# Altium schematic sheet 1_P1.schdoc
size 309 x 223 mm; Symbol: Sheet-Symbol_A4; Device: Sheet-Symbol_A4; Company: 嘉立创EDA; Version: V1.0; Page Size: A4; @Project Name: 阿尔法波平板; @Page Count: 1; @Update Date: 2024-05-21; @Create Date: 2024-05-20; @Schematic Name: Schematic1; @Page No: 1; @Page Name: P1
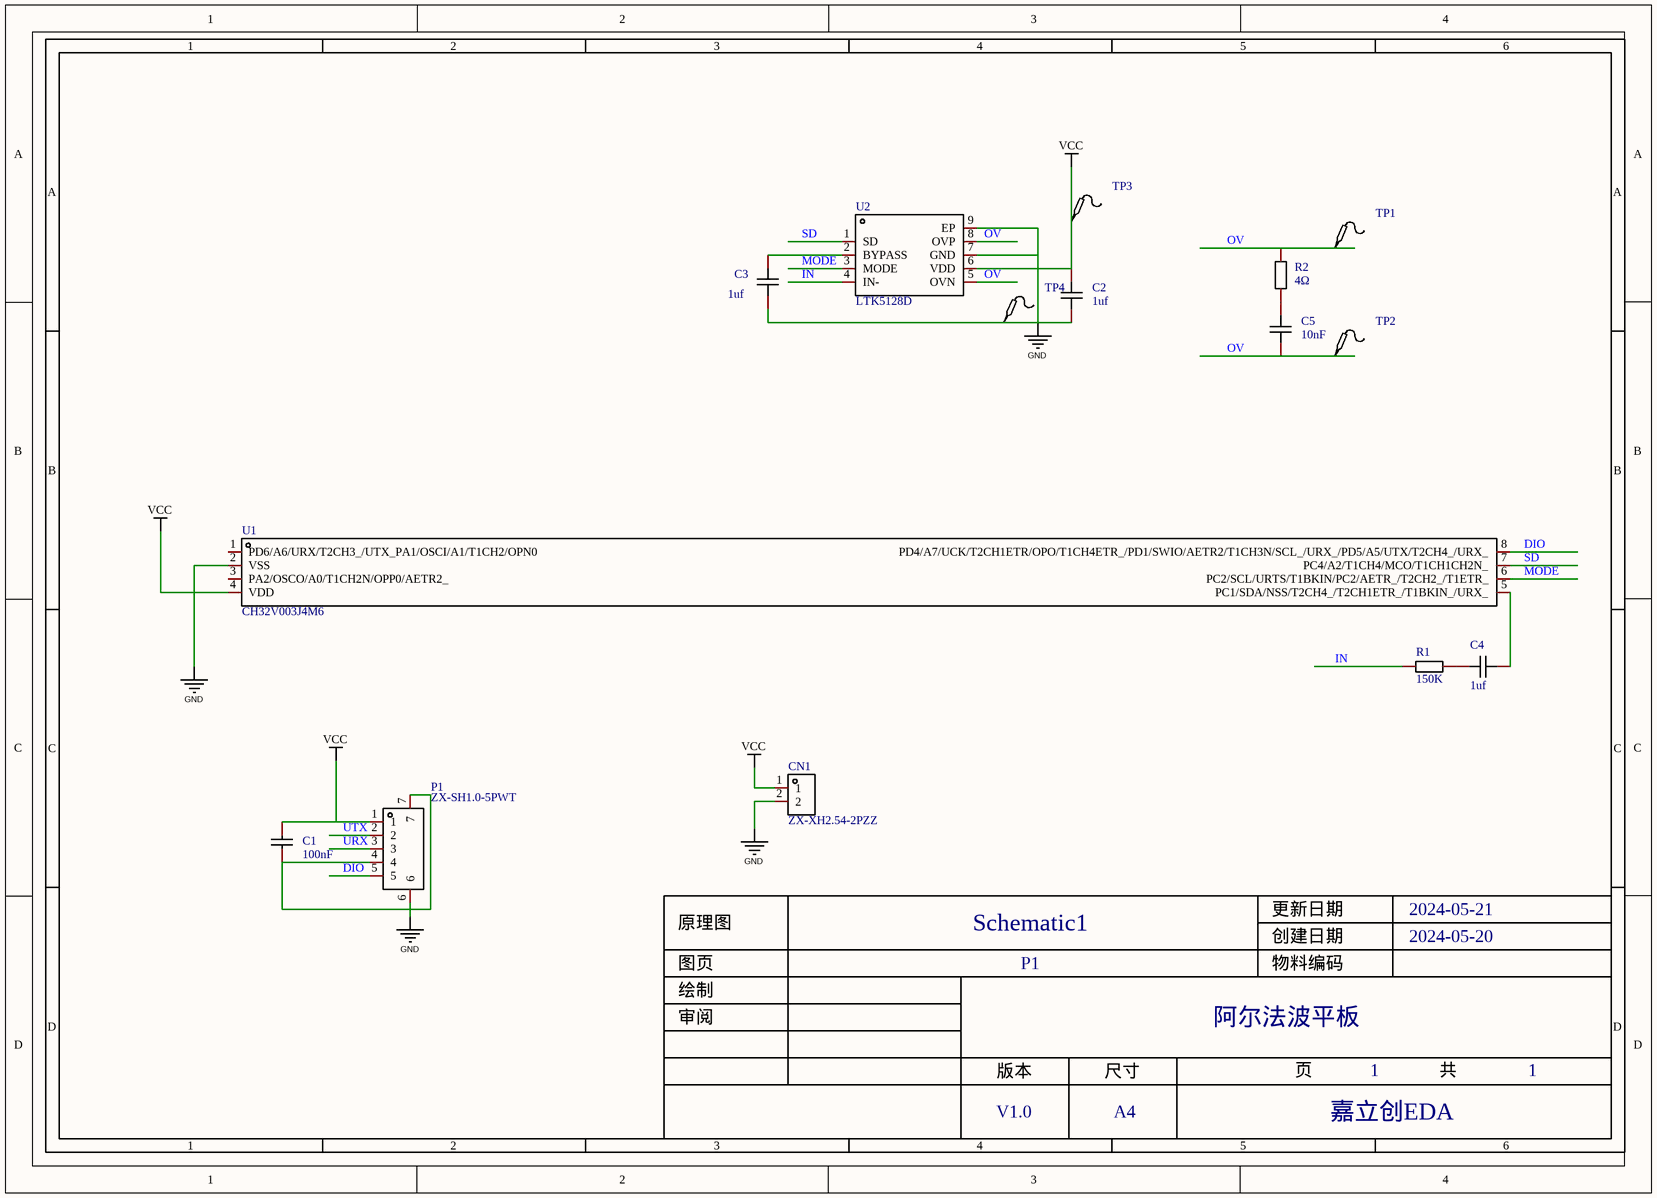
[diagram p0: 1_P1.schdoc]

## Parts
C1  100nF  [C0603]
C2  1uf  [C0603]
C3  1uf  [C0603]
C4  1uf  [C0603]
C5  10nF  [C0603]
CN1  ZX-XH2.54-2PZZ  [CONN-TH_2P-P2.50_HX25003-2A]
P1  ZX-SH1.0-5PWT  [CONN-SMD_5P-P1.00_MEGASTAR_ZX-SH1.0-5PWT]
R1  150K  [R0603]
R2  4Ω  [R0603]
TP1  Test-Point  [Test-Point-0.5mm]  (value not drawn)
TP2  Test-Point  [Test-Point-0.5mm]  (value not drawn)
TP3  Test-Point  [Test-Point-0.5mm]  (value not drawn)
TP4  Test-Point  [Test-Point-0.5mm]  (value not drawn)
U1  CH32V003J4M6  [SOP-8_L4.9-W3.8-P1.27-LS6.0-BL]
U2  LTK5128D  [ESOP-8_L4.9-W3.9-P1.27-LS6.0-BL-EP]

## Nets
GND: C1.1 C2.1 C3.1 CN1.2 P1.4 P1.6 P1.7 TP4.1 U1.2(VSS) U2.7(GND) U2.9(EP)
VCC: C1.2 C2.2 CN1.1 P1.1 TP3.1 U1.4(VDD) U2.6(VDD)
DIO: P1.5 U1.8(PD4/A7/UCK/T2CH1ETR/OPO/T1CH4ETR_/PD1/SWIO/AETR2/T1CH3N/SCL_/URX_/PD5/A5/UTX/T2CH4_/URX_)
IN: R1.1 U2.4(IN-)
MODE: U1.6(PC2/SCL/URTS/T1BKIN/PC2/AETR_/T2CH2_/T1ETR_) U2.3(MODE)
OV: C5.1 R2.2 TP1.1 TP2.1 U2.5(OVN) U2.8(OVP)
SD: U1.7(PC4/A2/T1CH4/MCO/T1CH1CH2N_) U2.1(SD)
URX: P1.3
UTX: P1.2
NetC3_2: C3.2 U2.2(BYPASS)
NetC4_1: C4.1 U1.5(PC1/SDA/NSS/T2CH4_/T2CH1ETR_/T1BKIN_/URX_)
NetC4_2: C4.2 R1.2
NetC5_2: C5.2 R2.1

Not connected (* = marked no-connect by the designer): U1 1(PD6/A6/URX/T2CH3_/UTX_PA1/OSCI/A1/T1CH2/OPN0) 3(PA2/OSCO/A0/T1CH2N/OPP0/AETR2_)

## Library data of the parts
C1 = 0603B104K500NT: 容值:100nF;精度:±10%;额定电压:50V;材质(温度系数):X7R;; Manufacturer: FH(风华); Add into BOM: yes; Tolerance: ±10%; Voltage Rated: 50V; Temperature Coefficient: X7R
C2-C5 = CAP_0603: Symbol: CapAcitance; Convert to PCB: yes
CN1 = ZX-XH2.54-2PZZ: 插针结构:1x2P;间距:2.54mm;安装方式:直插;参考系列:XH;总PIN数:2P;排数:1;每排PIN数:2;行距:-;额定电流:3A;触头材质:黄铜;触头镀层:锡;工作温度范围:-25℃~+85℃;; Manufacturer: Megastar(兆星); Add into BOM: yes; Pins Structure: 1x2P; Pitch: 2.54mm; Reference Series: XH; Number of PINs Per Row: 2; Current Rating (Max): 3A
P1 = ZX-SH1.0-5PWT: 插针结构:1x5P;间距:1mm;安装方式:卧贴;参考系列:SH;总PIN数:5P;排数:1;每排PIN数:5;行距:-;额定电流:1A;触头材质:黄铜;触头镀层:锡;工作温度范围:-25℃~+85℃;; Manufacturer: Megastar(兆星); Add into BOM: yes; Pins Structure: 1x5P; Pitch: 1mm; Reference Series: SH; Number of PINs Per Row: 5; Current Rating (Max): 1A
R1 R2 = Res_0603: Symbol: 电阻; Convert to PCB: yes
TP1-TP4 = Test-Point: Test Point 测试点; Add into BOM: yes
U1 = CH32V003J4M6_C5346354: Manufacturer: WCH(南京沁恒); Add into BOM: yes
U2 = LTK5128D: 功放类型:-;输出功率:-;; Manufacturer: LTKCHIP(联辉科); Add into BOM: yes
